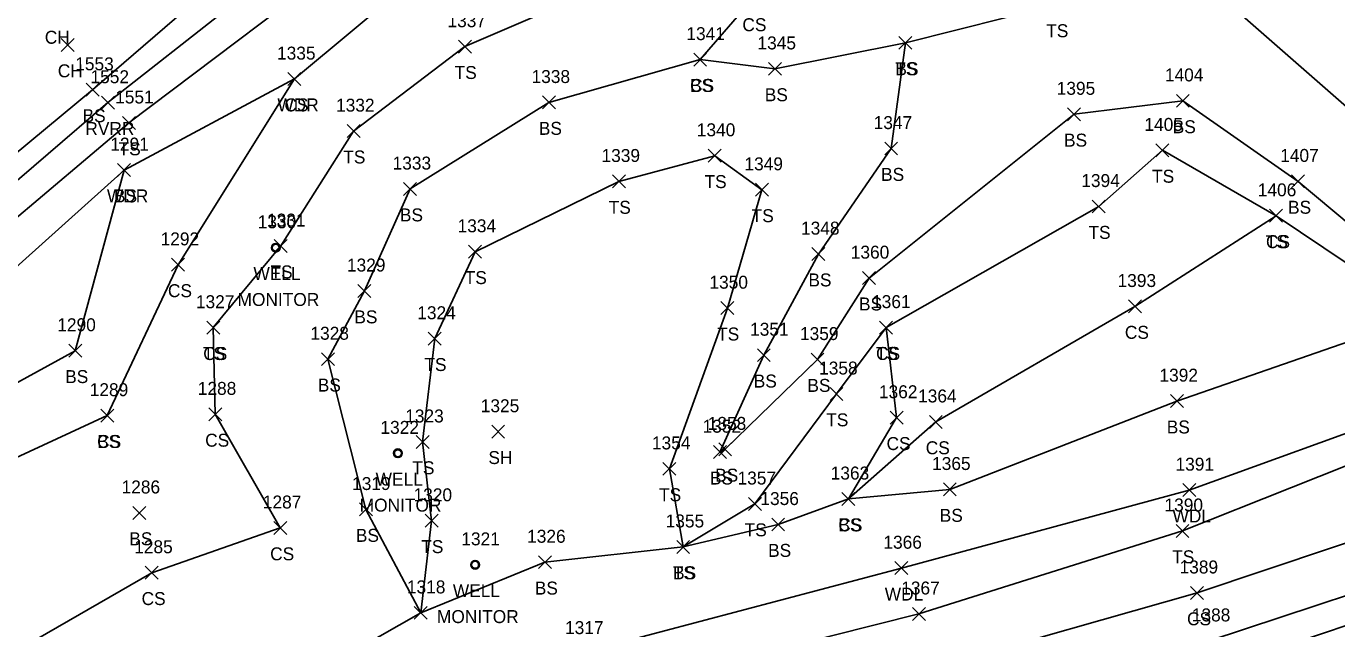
# Model space of a CAD drawing. Extents: x 1443064 to 1445163, y 544063 to 544655.
# Drawn here: x 1443463.7 to 1443666.1, y 544308.2 to 544401.2 of the extents above; entities that cross this region are included whole.
import ezdxf

# ---------------------------------------------------------------- set-up
doc = ezdxf.new("R2010")
doc.units = 0
for name, color, linetype in [('L_A', 7, 'Continuous'), ('L_I', 7, 'Continuous'), ('L_TIC', 7, 'Continuous'), ('LAWA', 7, 'Continuous'), ('LAWE', 7, 'Continuous'), ('LELB', 7, 'Continuous'), ('PET', 7, 'Continuous'), ('U_A', 7, 'Continuous'), ('U_C', 7, 'Continuous'), ('U_I', 7, 'Continuous'), ('UWW', 7, 'Continuous')]:
    doc.layers.add(name, color=color, linetype=linetype)

msp = doc.modelspace()

# ---------------------------------------------------------------- linework, layer by layer
at = {"layer": 'L_TIC'}
for points in [[(1443598.52, 544397.63), (1443600.52, 544399.63)], [(1443600.52, 544397.63), (1443598.52, 544399.63)], [(1443598.52, 544397.63), (1443600.52, 544399.63)], [(1443600.52, 544397.63), (1443598.52, 544399.63)], [(1443469.1, 544397.31), (1443471.1, 544399.31)], [(1443471.1, 544397.31), (1443469.1, 544399.31)], [(1443530.47, 544397.05), (1443532.47, 544399.05)], [(1443532.47, 544397.05), (1443530.47, 544399.05)], [(1443566.81, 544395.05), (1443568.81, 544397.05)], [(1443568.81, 544395.05), (1443566.81, 544397.05)], [(1443566.81, 544395.05), (1443568.81, 544397.05)], [(1443568.81, 544395.05), (1443566.81, 544397.05)], [(1443578.35, 544393.62), (1443580.35, 544395.62)], [(1443580.35, 544393.62), (1443578.35, 544395.62)], [(1443504.14, 544392.05), (1443506.14, 544394.05)], [(1443506.14, 544392.05), (1443504.14, 544394.05)], [(1443504.14, 544392.05), (1443506.14, 544394.05)], [(1443506.14, 544392.05), (1443504.14, 544394.05)], [(1443472.97, 544390.39), (1443474.97, 544392.39)], [(1443474.97, 544390.39), (1443472.97, 544392.39)], [(1443475.33, 544388.4), (1443477.33, 544390.4)], [(1443477.33, 544388.4), (1443475.33, 544390.4)], [(1443543.45, 544388.43), (1443545.45, 544390.43)], [(1443545.45, 544388.43), (1443543.45, 544390.43)], [(1443641.36, 544388.68), (1443643.36, 544390.68)], [(1443643.36, 544388.68), (1443641.36, 544390.68)], [(1443624.57, 544386.61), (1443626.57, 544388.61)], [(1443626.57, 544386.61), (1443624.57, 544388.61)], [(1443478.57, 544385.27), (1443480.57, 544387.27)], [(1443480.57, 544385.27), (1443478.57, 544387.27)], [(1443513.27, 544384.01), (1443515.27, 544386.01)], [(1443515.27, 544384.01), (1443513.27, 544386.01)], [(1443569.07, 544380.21), (1443571.07, 544382.21)], [(1443571.07, 544380.21), (1443569.07, 544382.21)], [(1443596.31, 544381.32), (1443598.31, 544383.32)], [(1443598.31, 544381.32), (1443596.31, 544383.32)], [(1443638.2, 544381.04), (1443640.2, 544383.04)], [(1443640.2, 544381.04), (1443638.2, 544383.04)], [(1443477.82, 544378), (1443479.82, 544380)], [(1443479.82, 544378), (1443477.82, 544380)], [(1443477.82, 544378), (1443479.82, 544380)], [(1443479.82, 544378), (1443477.82, 544380)], [(1443554.27, 544376.24), (1443556.27, 544378.24)], [(1443556.27, 544376.24), (1443554.27, 544378.24)], [(1443659.17, 544376.25), (1443661.17, 544378.25)], [(1443661.17, 544376.25), (1443659.17, 544378.25)], [(1443521.99, 544375.07), (1443523.99, 544377.07)], [(1443523.99, 544375.07), (1443521.99, 544377.07)], [(1443576.35, 544374.95), (1443578.35, 544376.95)], [(1443578.35, 544374.95), (1443576.35, 544376.95)], [(1443628.38, 544372.37), (1443630.38, 544374.37)], [(1443630.38, 544372.37), (1443628.38, 544374.37)], [(1443655.76, 544370.94), (1443657.76, 544372.94)], [(1443657.76, 544370.94), (1443655.76, 544372.94)], [(1443655.76, 544370.94), (1443657.76, 544372.94)], [(1443657.76, 544370.94), (1443655.76, 544372.94)], [(1443502.03, 544366.27), (1443504.03, 544368.27)], [(1443504.03, 544366.27), (1443502.03, 544368.27)], [(1443532.03, 544365.39), (1443534.03, 544367.39)], [(1443534.03, 544365.39), (1443532.03, 544367.39)], [(1443486.16, 544363.37), (1443488.16, 544365.37)], [(1443488.16, 544363.37), (1443486.16, 544365.37)], [(1443585.08, 544365.03), (1443587.08, 544367.03)], [(1443587.08, 544365.03), (1443585.08, 544367.03)], [(1443592.9, 544361.32), (1443594.9, 544363.32)], [(1443594.9, 544361.32), (1443592.9, 544363.32)], [(1443514.95, 544359.33), (1443516.95, 544361.33)], [(1443516.95, 544359.33), (1443514.95, 544361.33)], [(1443571.02, 544356.68), (1443573.02, 544358.68)], [(1443573.02, 544356.68), (1443571.02, 544358.68)], [(1443633.97, 544356.94), (1443635.97, 544358.94)], [(1443635.97, 544356.94), (1443633.97, 544358.94)], [(1443491.61, 544353.67), (1443493.61, 544355.67)], [(1443493.61, 544353.67), (1443491.61, 544355.67)], [(1443491.61, 544353.67), (1443493.61, 544355.67)], [(1443493.61, 544353.67), (1443491.61, 544355.67)], [(1443595.53, 544353.68), (1443597.53, 544355.68)], [(1443597.53, 544353.68), (1443595.53, 544355.68)], [(1443595.53, 544353.68), (1443597.53, 544355.68)], [(1443597.53, 544353.68), (1443595.53, 544355.68)], [(1443525.8, 544351.97), (1443527.8, 544353.97)], [(1443527.8, 544351.97), (1443525.8, 544353.97)], [(1443470.29, 544350.11), (1443472.29, 544352.11)], [(1443472.29, 544350.11), (1443470.29, 544352.11)], [(1443576.64, 544349.42), (1443578.64, 544351.42)], [(1443578.64, 544349.42), (1443576.64, 544351.42)], [(1443509.31, 544348.8), (1443511.31, 544350.8)], [(1443511.31, 544348.8), (1443509.31, 544350.8)], [(1443584.93, 544348.75), (1443586.93, 544350.75)], [(1443586.93, 544348.75), (1443584.93, 544350.75)], [(1443587.87, 544343.43), (1443589.87, 544345.43)], [(1443589.87, 544343.43), (1443587.87, 544345.43)], [(1443640.44, 544342.33), (1443642.44, 544344.33)], [(1443642.44, 544342.33), (1443640.44, 544344.33)], [(1443475.22, 544340.09), (1443477.22, 544342.09)], [(1443477.22, 544340.09), (1443475.22, 544342.09)], [(1443475.22, 544340.09), (1443477.22, 544342.09)], [(1443477.22, 544340.09), (1443475.22, 544342.09)], [(1443491.91, 544340.29), (1443493.91, 544342.29)], [(1443493.91, 544340.29), (1443491.91, 544342.29)], [(1443597.16, 544339.77), (1443599.16, 544341.77)], [(1443599.16, 544339.77), (1443597.16, 544341.77)], [(1443603.21, 544339.12), (1443605.21, 544341.12)], [(1443605.21, 544339.12), (1443603.21, 544341.12)], [(1443535.61, 544337.61), (1443537.61, 544339.61)], [(1443537.61, 544337.61), (1443535.61, 544339.61)], [(1443523.94, 544336.03), (1443525.94, 544338.03)], [(1443525.94, 544336.03), (1443523.94, 544338.03)], [(1443570.67, 544334.89), (1443572.67, 544336.89)], [(1443572.67, 544334.89), (1443570.67, 544336.89)], [(1443569.87, 544334.45), (1443571.87, 544336.45)], [(1443571.87, 544334.45), (1443569.87, 544336.45)], [(1443562.05, 544331.87), (1443564.05, 544333.87)], [(1443564.05, 544331.87), (1443562.05, 544333.87)], [(1443589.71, 544327.22), (1443591.71, 544329.22)], [(1443591.71, 544327.22), (1443589.71, 544329.22)], [(1443589.71, 544327.22), (1443591.71, 544329.22)], [(1443591.71, 544327.22), (1443589.71, 544329.22)], [(1443605.37, 544328.69), (1443607.37, 544330.69)], [(1443607.37, 544328.69), (1443605.37, 544330.69)], [(1443642.36, 544328.59), (1443644.36, 544330.59)], [(1443644.36, 544328.59), (1443642.36, 544330.59)], [(1443480.19, 544325.07), (1443482.19, 544327.07)], [(1443482.19, 544325.07), (1443480.19, 544327.07)], [(1443515.19, 544325.6), (1443517.19, 544327.6)], [(1443517.19, 544325.6), (1443515.19, 544327.6)], [(1443575.27, 544326.45), (1443577.27, 544328.45)], [(1443577.27, 544326.45), (1443575.27, 544328.45)], [(1443501.95, 544322.75), (1443503.95, 544324.75)], [(1443503.95, 544322.75), (1443501.95, 544324.75)], [(1443525.32, 544323.86), (1443527.32, 544325.86)], [(1443527.32, 544323.86), (1443525.32, 544325.86)], [(1443578.86, 544323.28), (1443580.86, 544325.28)], [(1443580.86, 544323.28), (1443578.86, 544325.28)], [(1443641.31, 544322.29), (1443643.31, 544324.29)], [(1443643.31, 544322.29), (1443641.31, 544324.29)], [(1443564.18, 544319.82), (1443566.18, 544321.82)], [(1443566.18, 544319.82), (1443564.18, 544321.82)], [(1443564.18, 544319.82), (1443566.18, 544321.82)], [(1443566.18, 544319.82), (1443564.18, 544321.82)], [(1443542.83, 544317.46), (1443544.83, 544319.46)], [(1443544.83, 544317.46), (1443542.83, 544319.46)], [(1443482.09, 544315.84), (1443484.09, 544317.84)], [(1443484.09, 544315.84), (1443482.09, 544317.84)], [(1443597.9, 544316.54), (1443599.9, 544318.54)], [(1443599.9, 544316.54), (1443597.9, 544318.54)], [(1443643.56, 544312.72), (1443645.56, 544314.72)], [(1443645.56, 544312.72), (1443643.56, 544314.72)], [(1443523.64, 544309.64), (1443525.64, 544311.64)], [(1443525.64, 544309.64), (1443523.64, 544311.64)], [(1443523.64, 544309.64), (1443525.64, 544311.64)], [(1443525.64, 544309.64), (1443523.64, 544311.64)], [(1443523.64, 544309.64), (1443525.64, 544311.64)], [(1443525.64, 544309.64), (1443523.64, 544311.64)], [(1443600.6, 544309.47), (1443602.6, 544311.47)], [(1443602.6, 544309.47), (1443600.6, 544311.47)]]:
    msp.add_lwpolyline(points, dxfattribs=at)
at = {"layer": 'LAWA'}
for points in [[(1443328.33, 544272.01), (1443354.38, 544286), (1443377.17, 544299.62), (1443408.35, 544324.23), (1443444.34, 544348.07), (1443478.82, 544379), (1443505.14, 544393.05), (1443523.9, 544408.72), (1443558.4, 544420.46), (1443603.2, 544442.99), (1443623.82, 544449.76), (1443648.97, 544490.11)], [(1443161.29, 544157.23), (1443186.09, 544163.69), (1443194.34, 544166.63), (1443196.33, 544167.63), (1443201.36, 544168), (1443240.97, 544179.17), (1443262.42, 544188.86), (1443303.08, 544207.19), (1443347.02, 544222.79), (1443391.79, 544240.14), (1443432.68, 544254.71), (1443466.61, 544275.19), (1443493.21, 544282.75), (1443512.25, 544287.37), (1443549.07, 544304.36), (1443598.9, 544317.54), (1443643.36, 544329.59), (1443677.18, 544341.83), (1443688.03, 544341.71), (1443709.45, 544338.47), (1443741.32, 544354.61), (1443794.32, 544372.46), (1443818.98, 544380.86)]]:
    msp.add_lwpolyline(points, dxfattribs=at)
at = {"layer": 'LAWE'}
msp.add_lwpolyline([(1443627.73, 544516.96), (1443602.93, 544465.06), (1443560.09, 544445.87), (1443514.11, 544419.1), (1443476.33, 544389.4), (1443439.4, 544357.75), (1443402.97, 544339.11), (1443368.14, 544318.06), (1443323.16, 544292.42), (1443281.44, 544273.46), (1443240.37, 544261.14), (1443193.33, 544260.65), (1443164.34, 544237.83), (1443139.78, 544220.74), (1443138.28, 544217.17), (1443133.77, 544210.32), (1443100.97, 544202.05)], dxfattribs=at)
at = {"layer": 'LELB'}
for points in [[(1443623.25, 544521.72), (1443599.67, 544467.52), (1443557.8, 544451.16), (1443512.32, 544424.47), (1443473.97, 544391.39), (1443436.99, 544360.77), (1443402.58, 544340.48), (1443365.21, 544324.82), (1443319.81, 544300.23), (1443279.76, 544280.29), (1443239.01, 544265.94), (1443191.15, 544266.77), (1443161, 544250.15), (1443130.5, 544221.16), (1443098.72, 544215.41)], [(1443630.6, 544513.66), (1443606.19, 544459.79), (1443563.47, 544440.26), (1443516.58, 544414.23), (1443479.57, 544386.27), (1443441.49, 544354.15), (1443406.03, 544333.57), (1443372.48, 544309.35), (1443326.54, 544284.19), (1443284.74, 544264.48), (1443242.9, 544256.57), (1443195.74, 544252.68), (1443182.88, 544237.49), (1443172.34, 544228.16)], [(1443623.82, 544449.76), (1443627.68, 544433.27), (1443634.47, 544420.35), (1443646.64, 544407.16), (1443670.1, 544386.6), (1443678.81, 544376.49), (1443690.38, 544361.22)], [(1443492.61, 544354.67), (1443503.03, 544367.27), (1443514.27, 544385.01), (1443531.47, 544398.05), (1443561.75, 544411.07), (1443611.15, 544427.85), (1443627.68, 544433.27)], [(1443567.81, 544396.05), (1443575.89, 544405.43), (1443618.15, 544417.13), (1443634.47, 544420.35)], [(1443599.52, 544398.63), (1443622.85, 544404.5), (1443646.64, 544407.16)], [(1443524.64, 544310.64), (1443516.19, 544326.6), (1443510.31, 544349.8), (1443515.95, 544360.33), (1443522.99, 544376.07), (1443544.45, 544389.43), (1443567.81, 544396.05), (1443579.35, 544394.62), (1443599.52, 544398.63), (1443597.31, 544382.32), (1443586.08, 544366.03), (1443577.64, 544350.42), (1443570.87, 544335.45), (1443571.67, 544335.89), (1443585.93, 544349.75), (1443593.9, 544362.32), (1443625.57, 544387.61), (1443642.36, 544389.68), (1443660.17, 544377.25), (1443671.17, 544368.04), (1443679.77, 544354.99)], [(1443348.08, 544245.71), (1443367.85, 544273.1), (1443385.57, 544289.21), (1443415.45, 544309.3), (1443446.5, 544327.39), (1443476.22, 544341.09), (1443487.16, 544364.37), (1443505.14, 544393.05)], [(1443524.64, 544310.64), (1443526.32, 544324.86), (1443524.94, 544337.03), (1443526.8, 544352.97), (1443533.03, 544366.39), (1443555.27, 544377.24), (1443570.07, 544381.21), (1443577.35, 544375.95), (1443572.02, 544357.68), (1443563.05, 544332.87), (1443565.18, 544320.82), (1443576.27, 544327.45), (1443588.87, 544344.43), (1443596.53, 544354.68), (1443629.38, 544373.37), (1443639.2, 544382.04), (1443656.76, 544371.94), (1443667.92, 544364.45), (1443674.4, 544354.73)], [(1443073.59, 544128.34), (1443116.66, 544141.89), (1443162.8, 544149.75), (1443198.07, 544157.24), (1443242.5, 544173.41), (1443262.84, 544182.05), (1443307.11, 544199.46), (1443348.85, 544214.35), (1443394.74, 544233.02), (1443435.02, 544243.93), (1443473.16, 544259.47), (1443514.32, 544272.16), (1443555.56, 544285.54), (1443605.06, 544302.52), (1443644.56, 544313.72), (1443676.09, 544324.26), (1443689.45, 544326.75), (1443708.55, 544330.01), (1443714.07, 544333.45), (1443742.84, 544349.83), (1443793.92, 544368.99), (1443822.61, 544377.56)], [(1443074.67, 544122.4), (1443120.32, 544131.74), (1443165.11, 544143.77), (1443199.58, 544153.13), (1443245.24, 544167.88), (1443264.59, 544177.57), (1443308.86, 544194.48), (1443350.56, 544209.36), (1443397.32, 544225.82), (1443437.1, 544238.98), (1443476.53, 544253.14), (1443516.75, 544265.8), (1443558.95, 544280.95), (1443607.52, 544296.39), (1443646.45, 544306.32), (1443685.12, 544319.06), (1443714.26, 544329.16), (1443721.31, 544331.26), (1443744.28, 544345.57), (1443795.65, 544366.53), (1443822.61, 544377.56)], [(1443343.36, 544234.64), (1443341.34, 544245.28), (1443362.31, 544278.45), (1443382.08, 544293.73), (1443410.77, 544317.09), (1443446.9, 544337.74), (1443471.29, 544351.11), (1443478.82, 544379)], [(1443596.53, 544354.68), (1443598.16, 544340.77), (1443590.71, 544328.22), (1443604.21, 544340.12), (1443634.97, 544357.94), (1443656.76, 544371.94)], [(1443298.3, 544219.12), (1443343.36, 544234.64), (1443347.13, 544235.69), (1443361.65, 544240.04), (1443373.89, 544246.37), (1443387.28, 544254.4), (1443426.15, 544267.88), (1443461.49, 544286.76), (1443487.3, 544295.55), (1443508.64, 544301.52), (1443524.64, 544310.64), (1443543.83, 544318.46), (1443565.18, 544320.82), (1443579.86, 544324.28), (1443590.71, 544328.22), (1443606.37, 544329.69), (1443641.44, 544343.33), (1443674.4, 544354.73), (1443679.77, 544354.99), (1443682.99, 544355.5), (1443689.34, 544351.28), (1443707.83, 544344.95), (1443741.32, 544354.61)], [(1443361.65, 544240.04), (1443365.6, 544252.15), (1443382.87, 544266.28), (1443423.93, 544281.08), (1443455.64, 544301.02), (1443483.09, 544316.84), (1443502.95, 544323.75), (1443492.91, 544341.29), (1443492.61, 544354.67)], [(1443466.61, 544275.19), (1443490.52, 544288.37), (1443512.25, 544287.37), (1443553.95, 544298.49), (1443601.6, 544310.47), (1443642.31, 544323.29), (1443675.99, 544336.7), (1443688, 544336.24), (1443698.55, 544337.96), (1443699.43, 544334.12), (1443708.55, 544330.01)]]:
    msp.add_lwpolyline(points, dxfattribs=at)
at = {"layer": 'PET'}
msp.add_lwpolyline([(1443075.39, 544117.71), (1443121.41, 544129.24), (1443165.99, 544140.07), (1443200.71, 544149.88), (1443246.42, 544165.39), (1443265.96, 544172.48), (1443311.2, 544187.88), (1443352.92, 544202.76), (1443399.28, 544220.13), (1443438.78, 544233.67), (1443478.75, 544247.35), (1443518.41, 544260.6), (1443561.23, 544274.05), (1443611.7, 544290.5), (1443646.84, 544301.68), (1443684.98, 544314.55), (1443724.57, 544327.54), (1443735.41, 544331.22), (1443748.81, 544336.36), (1443799.43, 544353.96), (1443827.31, 544364.14)], dxfattribs=at)
at = {"layer": 'UWW'}
for centre, radius in [((1443502.25, 544367.01), 0.667), ((1443502.25, 544367.01), 0.625), ((1443502.25, 544367.01), 0.583), ((1443502.25, 544367.01), 0.542), ((1443521.12, 544335.27), 0.667), ((1443521.12, 544335.27), 0.625), ((1443521.12, 544335.27), 0.583), ((1443521.12, 544335.27), 0.542), ((1443533.05, 544318.06), 0.667), ((1443533.05, 544318.06), 0.625), ((1443533.05, 544318.06), 0.583), ((1443533.05, 544318.06), 0.542)]:
    msp.add_circle(centre, radius, dxfattribs=at)

# ---------------------------------------------------------------- texts
at = {"layer": 'L_A'}
for s, p in [('CS', (1443574.33, 544400.43)), ('CH', (1443466.58, 544398.49)), ('TS', (1443621.26, 544399.5)), ('TS', (1443597.93, 544393.63)), ('BS', (1443597.96, 544393.63)), ('CH', (1443468.59, 544393.31)), ('TS', (1443529.88, 544393.05)), ('CS', (1443566.25, 544391.05)), ('BS', (1443566.25, 544391.05)), ('BS', (1443577.79, 544389.62)), ('WDR', (1443502.51, 544388.05)), ('CS', (1443503.59, 544388.05)), ('BS', (1443472.41, 544386.39)), ('RVRR', (1443472.84, 544384.4)), ('BS', (1443542.89, 544384.43)), ('BS', (1443640.8, 544384.68)), ('BS', (1443624.01, 544382.61)), ('TS', (1443477.98, 544381.27)), ('TS', (1443512.68, 544380.01)), ('BS', (1443595.75, 544377.32)), ('TS', (1443568.48, 544376.21)), ('TS', (1443637.61, 544377.04)), ('WDR', (1443476.18, 544374)), ('BS', (1443477.26, 544374)), ('TS', (1443553.68, 544372.24)), ('BS', (1443658.61, 544372.25)), ('BS', (1443521.43, 544371.07)), ('TS', (1443575.76, 544370.95)), ('TS', (1443627.79, 544368.37)), ('TS', (1443655.17, 544366.94)), ('CS', (1443655.2, 544366.94)), ('TS', (1443501.44, 544362.27)), ('TS', (1443531.44, 544361.39)), ('CS', (1443485.6, 544359.37)), ('BS', (1443584.53, 544361.03)), ('BS', (1443592.34, 544357.32)), ('BS', (1443514.39, 544355.33)), ('TS', (1443570.43, 544352.68)), ('CS', (1443633.41, 544352.94)), ('TS', (1443491.02, 544349.67)), ('CS', (1443491.05, 544349.67)), ('TS', (1443594.94, 544349.68)), ('CS', (1443594.97, 544349.68)), ('TS', (1443525.21, 544347.97)), ('BS', (1443469.73, 544346.11)), ('BS', (1443576.08, 544345.42)), ('BS', (1443508.75, 544344.8)), ('BS', (1443584.37, 544344.75)), ('TS', (1443587.28, 544339.43)), ('BS', (1443639.88, 544338.33)), ('CS', (1443474.66, 544336.09)), ('BS', (1443474.66, 544336.09)), ('CS', (1443491.35, 544336.29)), ('CS', (1443596.6, 544335.77)), ('CS', (1443602.65, 544335.12)), ('SH', (1443535.1, 544333.61)), ('TS', (1443523.35, 544332.03)), ('BS', (1443570.12, 544330.89)), ('BS', (1443569.31, 544330.45)), ('TS', (1443561.46, 544327.87)), ('BS', (1443604.81, 544324.69)), ('CS', (1443589.15, 544323.22)), ('BS', (1443589.15, 544323.22)), ('WDL', (1443640.77, 544324.59)), ('BS', (1443479.63, 544321.07)), ('BS', (1443514.63, 544321.6)), ('TS', (1443574.68, 544322.45)), ('CS', (1443501.39, 544318.75)), ('TS', (1443524.73, 544319.86)), ('BS', (1443578.3, 544319.28)), ('TS', (1443640.72, 544318.29)), ('TS', (1443563.59, 544315.82)), ('BS', (1443563.62, 544315.82)), ('BS', (1443542.27, 544313.46)), ('WDL', (1443596.32, 544312.54)), ('CS', (1443481.53, 544311.84)), ('CS', (1443643.01, 544308.72))]:
    msp.add_text(s, height=2, dxfattribs=at).set_placement(p)
at = {"layer": 'L_I'}
for s, p in [('1337', (1443528.78, 544401.05)), ('1341', (1443565.68, 544399.05)), ('1341', (1443565.68, 544399.05)), ('1345', (1443576.66, 544397.62)), ('1335', (1443502.45, 544396.05)), ('1335', (1443502.45, 544396.05)), ('1553', (1443471.28, 544394.39)), ('1552', (1443473.64, 544392.4)), ('1338', (1443541.76, 544392.43)), ('1404', (1443639.59, 544392.68)), ('1395', (1443622.88, 544390.61)), ('1551', (1443477.45, 544389.27)), ('1332', (1443511.57, 544388.01)), ('1340', (1443567.29, 544384.21)), ('1347', (1443594.61, 544385.32)), ('1405', (1443636.43, 544385.04)), ('1291', (1443476.7, 544382)), ('1291', (1443476.7, 544382)), ('1339', (1443552.57, 544380.24)), ('1407', (1443657.4, 544380.25)), ('1333', (1443520.3, 544379.07)), ('1349', (1443574.65, 544378.95)), ('1394', (1443626.68, 544376.37)), ('1406', (1443653.94, 544374.94)), ('1406', (1443653.94, 544374.94)), ('1331', (1443500.9, 544370.27)), ('1334', (1443530.34, 544369.39)), ('1292', (1443484.47, 544367.37)), ('1348', (1443583.39, 544369.03)), ('1360', (1443591.07, 544365.32)), ('1329', (1443513.25, 544363.33)), ('1350', (1443569.24, 544360.68)), ('1393', (1443632.28, 544360.94)), ('1327', (1443489.92, 544357.67)), ('1327', (1443489.92, 544357.67)), ('1361', (1443594.36, 544357.68)), ('1361', (1443594.36, 544357.68)), ('1324', (1443524.11, 544355.97)), ('1290', (1443468.51, 544354.11)), ('1351', (1443575.52, 544353.42)), ('1328', (1443507.61, 544352.8)), ('1359', (1443583.23, 544352.75)), ('1358', (1443586.18, 544347.43)), ('1392', (1443638.75, 544346.33)), ('1289', (1443473.52, 544344.09)), ('1289', (1443473.52, 544344.09)), ('1288', (1443490.21, 544344.29)), ('1362', (1443595.42, 544343.77)), ('1364', (1443601.47, 544343.12)), ('1325', (1443533.92, 544341.61)), ('1323', (1443522.25, 544340.03)), ('1353', (1443568.98, 544338.89)), ('1352', (1443568.18, 544338.45)), ('1354', (1443560.36, 544335.87)), ('1363', (1443587.97, 544331.22)), ('1363', (1443587.97, 544331.22)), ('1365', (1443603.63, 544332.69)), ('1391', (1443641.23, 544332.59)), ('1286', (1443478.44, 544329.07)), ('1319', (1443514.05, 544329.6)), ('1357', (1443573.58, 544330.45)), ('1287', (1443500.26, 544326.75)), ('1320', (1443523.54, 544327.86)), ('1356', (1443577.11, 544327.28)), ('1390', (1443639.53, 544326.29)), ('1355', (1443562.48, 544323.82)), ('1355', (1443562.48, 544323.82)), ('1326', (1443541.08, 544321.46)), ('1285', (1443480.39, 544319.84)), ('1366', (1443596.11, 544320.54)), ('1389', (1443641.86, 544316.72)), ('1318', (1443522.51, 544313.64)), ('1318', (1443522.51, 544313.64)), ('1318', (1443522.51, 544313.64)), ('1367', (1443598.86, 544313.47)), ('1388', (1443643.75, 544309.32)), ('1317', (1443546.94, 544307.36))]:
    msp.add_text(s, height=2, dxfattribs=at).set_placement(p)
at = {"layer": 'U_A'}
for p in [(1443498.81, 544362.01), (1443517.68, 544330.27), (1443529.61, 544313.06)]:
    msp.add_text('WELL', height=2, dxfattribs=at).set_placement(p)
at = {"layer": 'U_C'}
for p in [(1443496.35, 544358.01), (1443515.22, 544326.27), (1443527.15, 544309.06)]:
    msp.add_text('MONITOR', height=2, dxfattribs=at).set_placement(p)
at = {"layer": 'U_I'}
for s, p in [('1330', (1443499.47, 544370.01)), ('1322', (1443518.42, 544338.27)), ('1321', (1443530.92, 544321.06))]:
    msp.add_text(s, height=2, dxfattribs=at).set_placement(p)

doc.saveas('drawing.dxf')
